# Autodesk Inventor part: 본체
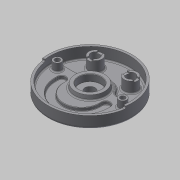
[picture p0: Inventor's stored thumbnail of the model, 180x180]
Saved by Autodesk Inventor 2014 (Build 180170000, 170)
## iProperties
Created: 2015-06
Part Number: 본체
Material: Generic
Document SubType Name: Modeling
Designer: MYHOME
Density: 1 g/cm^3
Appearance: Default
Mass: 397.026 g
Surface Area: 1040.74 cm^2
Volume: 397.026 cm^3
Author: MYHOME
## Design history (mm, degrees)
sketch "스케치1"
  geometry: C1 r 95 at (0, 0); 1 further point
  constraints: 1 centre point, 1 coincident
  dimensions: "d0" = 190 diameter of C1
extrude "돌출1" new body sketch "스케치1" distance "d1" = 32; taper "d2" = 0 deg
sketch "스케치2"
  geometry: C1 r 95 at (0, 0) reference; C2 r 90 at (0, 0)
  constraints: 1 centre point, 1 coincident
  dimensions: "d3" = 180 diameter of C2
extrude "돌출2" cut sketch "스케치2" distance "d4" = 25; taper "d5" = 0 deg
sketch "스케치3"
  geometry: L1 (-38.833, 16)-(-88.566, 16); L2 (38.833, 16)-(88.566, 16); C1 r 90 at (0, 0) reference; A1 r 42 centre (0, 0) between (38.833, 16) and (-38.833, 16); A2 r 90 centre (0, 0) between (-88.566, 16) and (88.566, 16)
  constraints: 4 end point, 4 point on circle, 2 centre point, 2 coincident, 1 collinear, 1 horizontal
  dimensions: "d6" = 84 diameter of A1; "d7" = 16 distance from line of A1.centre L1; "d8" = 16 distance from line of C1.centre L2; "d9" = 180 diameter of A2
extrude "돌출3" join sketch "스케치3" distance "d10" = 7; taper "d11" = 0 deg
fillet "모깎기1" dims "d12" = 10
sketch "스케치4"
  geometry: L1 (-95, 0)-(95, 0); L2 (0, 0)-(-94.075, -13.221); L3 (0, 0)-(94.075, -13.221); C1 r 90 at (0, 0) reference; C2 r 95 at (0, 0); A1 r 95 centre (0, 0) between (-95, 0) and (95, 0) reference; A2 r 90 centre (0, 0) between (-89.124, -12.526) and (89.124, -12.526); 2 further points
  constraints: 6 end point, 6 point on circle, 4 coincident, 2 centre point, 2 point on line, 1 horizontal, 1 midpoint
  dimensions: "d13" = 8 deg angle of L2 L1; "d14" = 8 deg angle of L3 L1; "d15" = 180 diameter of A2; "d16" = 190 diameter of C2
extrude "돌출4" cut sketch "스케치4" distance "d17" = 5; taper "d18" = 0 deg
sketch "스케치5"
  geometry: C1 r 35 at (0, 0); A1 r 90 centre (0, 0) between (-85.114, 29.25) and (85.114, 29.25) reference
  constraints: 1 centre point, 1 coincident
  dimensions: "d19" = 70 diameter of C1
extrude "돌출5" join sketch "스케치5" distance "d20" = 10; taper "d21" = -10 deg
sketch "스케치6"
  geometry: C1 r 95 at (0, 0) reference; C2 r 26 at (0, 0)
  constraints: 1 centre point, 1 coincident
  dimensions: "d22" = 52 diameter of C2
extrude "돌출6" join sketch "스케치6" distance "d23" = 12; taper "d24" = -15 deg
hole "구멍1" diameter "d27" = 23; stored, may be unused: countersink angle "d31" = 90 deg, drill point angle "d33" = 118 deg; dims "d25" = 10, "d26" = 10, "d28" = 6, "d29" = 50, "d30" = 15, "d32" = 8
sketch "스케치7"
  geometry: C1 r 15 at (-40, 52); C2 r 15 at (40, 52); C3 r 10 at (-40, 52); C4 r 10 at (40, 52); A1 r 90 centre (0, 0) between (85.114, 29.25) and (-85.114, 29.25) reference
  constraints: 4 centre point, 2 coincident, 1 horizontal alignment
  dimensions: "d34" = 30 diameter of C1; "d35" = 30 diameter of C2; "d36" = 52 vertical distance of C1.centre A1.centre; "d37" = 80 distance of C2.centre C1.centre; "d38" = 40 horizontal distance of A1.centre C1.centre; "d39" = 20 diameter of C3; "d40" = 20 diameter of C4
extrude "돌출7" join sketch "스케치7" stored distance "d41" = 12; taper "d42" = 0 deg
extrude "돌출8" cut sketch "스케치7" stored distance "d43" = 12; taper "d44" = 0 deg
sketch "스케치8"
  geometry: L1 (-6, 13.748)-(-6, -13.748); L2 (6, 13.748)-(6, -13.748); L3 (66.252, 6)-(93.748, 6); L4 (66.252, -6)-(93.748, -6); C1 r 10 at (0, 0) reference; C2 r 10 at (80, 0) reference; A1 r 15 centre (0, 0) between (6, 13.748) and (-6, 13.748) reference; A2 r 15 centre (80, 0) between (93.748, 6) and (93.748, -6) reference; A3 r 15 centre (0, 0) between (6, 13.748) and (-6, 13.748); A4 r 15 centre (0, 0) between (-6, -13.748) and (6, -13.748); A5 r 15 centre (80, 0) between (66.252, 6) and (66.252, -6); A6 r 15 centre (80, 0) between (93.748, -6) and (93.748, 6); 1 further point
  constraints: 16 point on circle, 8 end point, 4 centre point, 2 coincident, 2 parallel, 1 perpendicular, 1 vertical
  dimensions: "d45" = 6 distance from line of L2 C1.centre; "d46" = 12 distance between parallel lines of L2 L1; "d47" = 6 distance from line of L3 C2.centre; "d48" = 12 distance between parallel lines of L4 L3
extrude "돌출9" cut sketch "스케치8" distance "d49" = 3; taper "d50" = 0 deg
sketch "스케치9"
  geometry: C1 r 35 at (0, 0) reference; C2 r 9 at (-74, 0); C3 r 9 at (74, 0)
  constraints: 2 centre point, 2 horizontal alignment
  dimensions: "d51" = 18 diameter of C2; "d52" = 18 diameter of C3; "d53" = 148 distance of C3.centre C2.centre; "d54" = 74 distance of C3.centre C1.centre
extrude "돌출10" join sketch "스케치9" stored distance "d55" = 3; taper "d56" = 0 deg
sketch "스케치10"
  geometry: C1 r 9 at (74, 0) reference; C2 r 9 at (-74, 0) reference; 2 further points
  constraints: 2 coincident
hole "구멍2" sketch "스케치10" at (-74, 0), (74, 0) diameter "d57" = 11; stored, may be unused: countersink angle "d61" = 90 deg, drill point angle "d63" = 118 deg; dims "d58" = 6, "d59" = 18, "d60" = 11, "d62" = 8
sketch "스케치11"
  geometry: L1 (75.657, 16)-(45.033, 16) reference; L2 (59, -19)-(59, -14); L3 (41, -19)-(41, -14); L4 (-41, -19)-(-41, -14); L5 (-59, -19)-(-59, -14); L6 (59, -14)-(41, -14); L7 (-41, -14)-(-59, -14); C1 r 35 at (0, 0) reference; A1 r 42 centre (0, 0) between (36.373, 21) and (-36.373, 21) reference; A2 r 41 centre (0, -19) between (-41, -19) and (41, -19); A3 r 59 centre (0, -19) between (-59, -19) and (59, -19); A4 r 9 centre (50, -14) between (59, -14) and (41, -14); A5 r 9 centre (-50, -14) between (-41, -14) and (-59, -14)
  constraints: 12 end point, 8 point on circle, 4 centre point, 4 equal length, 4 horizontal alignment, 4 tangent, 2 midpoint, 2 perpendicular, 1 coincident, 1 collinear, 1 vertical alignment
  dimensions: "d66" = 19 distance of A2.centre C1.centre; "d67" = 41 radius of A2; "d68" = 59 radius of A3; "d69" = 5 distance of L2.start L2.end
extrude "돌출11" cut sketch "스케치11" distance "d70" = 7; taper "d71" = 0 deg
sketch "스케치12"
  geometry: C1 r 95 at (0, 0) reference; C2 r 68 at (0, 0)
  constraints: 1 centre point, 1 coincident, 1 other
  dimensions: "d72" = 136 diameter of C2
feature "엠보싱1" sketch "스케치12" dims "d1" = 32, "d73" = 0.5, "d74" = 0
fillet "모깎기3" dims "d76" = 3
fillet "모깎기4" dims "d77" = 3
fillet "모깎기5" dims "d78" = 3
fillet "모깎기6" dims "d79" = 1
fillet "모깎기7" dims "d80" = 0.3
chamfer "모따기1" distance "d81" = 1; stored, may be unused: second distance "d82" = 2, angle "d83" = 45 deg
fillet "모깎기8" dims "d84" = 3
fillet "모깎기9" dims "d85" = 3
fillet "모깎기10" dims "d86" = 3
fillet "모깎기11" dims "d87" = 5
node "솔리드1"
node "투영된 루프1"
node "투영된 루프2"
